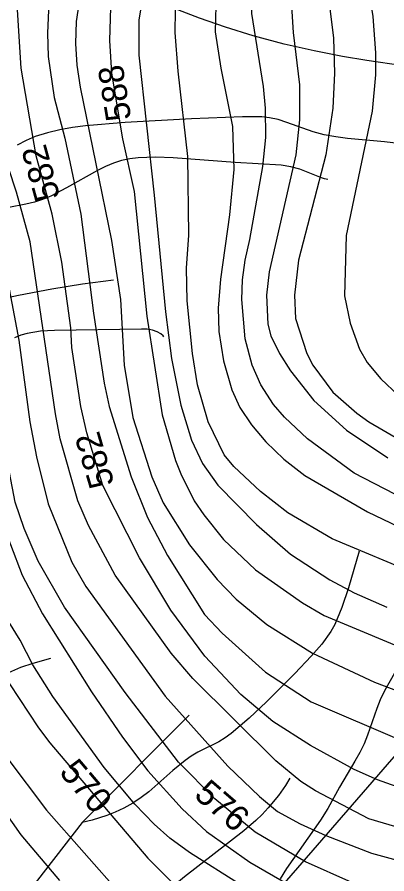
# Model space of a CAD drawing. Extents: x -709584 to -702006, y -1161789 to -1157496.
# Drawn here: x -709047.8 to -708901, y -1161172.4 to -1160832.7 of the extents above; entities that cross this region are included whole.
import ezdxf

# ---------------------------------------------------------------- set-up
doc = ezdxf.new("R2010")
doc.units = 0
for name, color, linetype in [('120_vrstevnice hlavní', 7, 'Continuous'), ('121_vrstevnice hlavní_popis', 7, 'Continuous'), ('122_vrstevnice základní', 7, 'Continuous'), ('411_akumulovaný odtok', 7, 'Continuous')]:
    doc.layers.add(name, color=color, linetype=linetype)

msp = doc.modelspace()

# ---------------------------------------------------------------- linework, layer by layer
at = {"layer": '120_vrstevnice hlavní'}
for points in [[(-708900.67, -1160565.36), (-708906.31, -1160597.76), (-708913.69, -1160630.16), (-708921.21, -1160653.3), (-708933.94, -1160685.7), (-708963.16, -1160745.88), (-708984.85, -1160787.53), (-708991.08, -1160801.42), (-708994.55, -1160810.68), (-708997.15, -1160819.93), (-708999.46, -1160833.82), (-708999.46, -1160847.71), (-708993.39, -1160903.25), (-708988.91, -1160949.54), (-708986.45, -1160968.05), (-708982.83, -1160986.56), (-708978.49, -1161000.45), (-708974.15, -1161009.71), (-708968.08, -1161018.24), (-708952.74, -1161033.86), (-708939.29, -1161045.58), (-708923.67, -1161055.85), (-708913.98, -1161060.91), (-708900.96, -1161066.7)], [(-708895.03, -1160707.69), (-708909.35, -1160738.07), (-708920.49, -1160764.1), (-708923.53, -1160773.07), (-708925.84, -1160782.33), (-708927.86, -1160794.8), (-708927.6, -1160807.53), (-708923.96, -1160827.17), (-708922.22, -1160841.05), (-708921.79, -1160854.94), (-708922.51, -1160868.82), (-708925.26, -1160887.34), (-708936.11, -1160929), (-708937.7, -1160942.88), (-708937.27, -1160952.14), (-708932.78, -1160966.03), (-708930.32, -1160970.65)], [(-708894.31, -1161154.64), (-708908.19, -1161150.59), (-708929.31, -1161139.45), (-708935.1, -1161135.84), (-708945.08, -1161127.59), (-708978.06, -1161094.9), (-708986.59, -1161084.92), (-709008.87, -1161053.97), (-709019.43, -1161034.3), (-709023.62, -1161024.46), (-709030.71, -1160999.87), (-709032.59, -1160990.04), (-709042.57, -1160921.76), (-709048.07, -1160902.09), (-709054.57, -1160882.42), (-709058.48, -1160867.67), (-709060.36, -1160852.91), (-709061.08, -1160838.16), (-709060.65, -1160823.7)], [(-709117.78, -1160829.48), (-709119.66, -1160842.5), (-709120.24, -1160855.52), (-709117.21, -1160884.16), (-709110.7, -1160908.46), (-709095.36, -1160959.08), (-709088.42, -1160993.8), (-709083.36, -1161024.17), (-709074.34, -1161055.36), (-709062.5, -1161079.58), (-709039.24, -1161114.57), (-709034.76, -1161120.51), (-708995.85, -1161166.21), (-708983.41, -1161178.65)], [(-708930.32, -1160970.65), (-708922.51, -1160981.36), (-708912.97, -1160989.75), (-708908.19, -1160993.22), (-708895.18, -1161000.74)]]:
    msp.add_lwpolyline(points, dxfattribs=at)
at = {"layer": '122_vrstevnice základní'}
for points in [[(-708893.44, -1160501.43), (-708905.01, -1160517.63), (-708917.74, -1160540.19), (-708923.38, -1160552.63), (-708928.88, -1160568.83), (-708936.54, -1160608.18), (-708944.35, -1160638.26), (-708950, -1160654.46), (-708959.69, -1160677.6), (-708965.62, -1160689.18), (-708975.31, -1160705.38), (-709010.75, -1160755.13), (-709017.4, -1160766.71), (-709020.73, -1160773.65), (-709027.09, -1160789.85), (-709032.3, -1160808.36), (-709033.75, -1160815.31), (-709035.19, -1160826.88), (-709035.77, -1160839.03), (-709035.48, -1160848.28), (-709033.02, -1160864.49)], [(-708896.48, -1160517.63), (-708903.28, -1160528.04), (-708912.82, -1160546.85), (-708920.63, -1160572.88), (-708931.34, -1160622.06), (-708935.1, -1160636.24), (-708939.44, -1160649.25), (-708949.85, -1160675.29), (-708959.69, -1160696.12), (-708968.08, -1160711.74), (-708979.36, -1160729.97), (-708995.27, -1160753.4), (-709003.95, -1160769.02), (-709014.65, -1160792.45), (-709021.59, -1160815.88), (-709024.34, -1160834.4), (-709024.63, -1160843.08), (-709024.05, -1160851.76), (-709022.75, -1160860.44), (-709010.31, -1160921.19), (-709006.7, -1160944.62), (-709005.25, -1160970.65), (-709001.78, -1160991.48), (-708994.26, -1161014.92)], [(-708887.94, -1161054.11), (-708922.66, -1161039.5), (-708940.3, -1161029.23), (-708951.15, -1161020.84), (-708961.71, -1161010.86), (-708965.62, -1161006.24), (-708971.98, -1160993.22), (-708976.18, -1160978.47), (-708978.2, -1160966.03), (-708980.23, -1160945.2), (-708980.52, -1160932.18), (-708979.65, -1160919.16), (-708979.94, -1160887.92), (-708983.8, -1160854.04), (-708985, -1160838.74), (-708984.85, -1160830.06), (-708982.83, -1160817.04), (-708973.43, -1160791.01), (-708959.69, -1160762.37), (-708954.05, -1160749.35), (-708923.96, -1160686.86), (-708911.38, -1160655.62), (-708905.16, -1160634.79), (-708899.95, -1160608.75)], [(-708898.65, -1160657.35), (-708907.9, -1160680.5), (-708959.69, -1160794.19), (-708964.75, -1160806.92), (-708968.8, -1160822.83), (-708969.09, -1160838.45), (-708966.92, -1160852.91), (-708962.29, -1160876.06), (-708961.75, -1160893.14), (-708963.45, -1160911.06), (-708967.06, -1160936.52), (-708967.93, -1160948.09), (-708967.64, -1160957.35), (-708965.91, -1160968.92), (-708962.58, -1160980.49), (-708959.4, -1160987.43), (-708954.77, -1160994.38), (-708948.98, -1161001.03), (-708941.9, -1161007.97), (-708933.51, -1161014.48), (-708908.63, -1161028.8), (-708887.37, -1161039.07)], [(-708897.78, -1161021.86), (-708913.98, -1161013.47), (-708932.49, -1160999.87), (-708941.61, -1160991.34), (-708945.95, -1160986.28), (-708951.01, -1160978.47), (-708954.48, -1160970.65), (-708957.23, -1160960.24), (-708958.53, -1160944.62), (-708958.24, -1160936.81), (-708957.23, -1160929), (-708955.35, -1160920.9), (-708950.29, -1160891.97), (-708948.98, -1160880.4), (-708949.13, -1160868.82), (-708950, -1160860.15), (-708954.62, -1160831.22), (-708954.62, -1160825.72), (-708953.18, -1160810.39), (-708948.39, -1160794.49), (-708933.94, -1160754.84), (-708914.7, -1160710.58), (-708897.63, -1160676.74)], [(-708891.13, -1160681.36), (-708902.7, -1160702.63), (-708918.46, -1160737.2), (-708930.76, -1160769.6), (-708934.52, -1160783.48), (-708938.57, -1160805.76), (-708939.29, -1160821.96), (-708938.14, -1160838.74), (-708935.68, -1160859.57), (-708935.68, -1160873.45), (-708937.12, -1160887.34), (-708947.68, -1160933.62), (-708948.84, -1160942.88), (-708948.26, -1160954.45), (-708947.1, -1160959.08), (-708943.63, -1160966.03), (-708939.29, -1160972.97), (-708930.04, -1160984.68), (-708917.02, -1160996.4), (-708900.67, -1161007.39)], [(-708911.81, -1160774.8), (-708912.74, -1160793.12), (-708906.6, -1160832.37), (-708905.45, -1160846.84), (-708905.45, -1160855.52), (-708906.89, -1160869.98), (-708917.1, -1160919.27), (-708917.86, -1160943.25), (-708915.59, -1160954.01), (-708911.81, -1160964.29), (-708908.77, -1160969.64), (-708903.42, -1160976.15), (-708896.33, -1160982.66)], [(-708893.15, -1161139.16), (-708904.72, -1161135.11), (-708913.98, -1161131.06), (-708931.34, -1161121.52), (-708946.23, -1161111.97), (-708958.96, -1161101.27), (-708973.28, -1161086.08), (-708986.73, -1161067.86), (-708999.18, -1161047.03), (-709013.78, -1161018.39), (-709020.15, -1160997.56), (-709022.46, -1160987.14), (-709026.08, -1160963.71), (-709026.51, -1160955.9), (-709029.98, -1160929.86), (-709033.89, -1160910.77), (-709040.25, -1160887.63), (-709046.18, -1160852.91), (-709047.63, -1160829.77), (-709046.47, -1160813.86), (-709042.57, -1160795.63), (-709037.22, -1160780.01)], [(-708958.82, -1161176.92), (-708979.36, -1161163.9), (-708987.17, -1161158.26), (-708993.39, -1161152.76), (-709001.06, -1161144.8), (-709013.21, -1161130.2), (-709033.6, -1161102.14), (-709041.56, -1161089.55), (-709046.62, -1161079.72), (-709056.74, -1161063.52), (-709062.29, -1161052.26), (-709067.83, -1161036.6), (-709071.06, -1161017.81), (-709078.44, -1160987.72), (-709081.91, -1160966.89), (-709088.42, -1160934.49), (-709094.21, -1160911.35), (-709096.52, -1160904.41), (-709102.02, -1160881.26), (-709104.77, -1160848.86), (-709104.33, -1160841.92), (-709101.29, -1160819.07)], [(-709125.88, -1160821.67), (-709128.2, -1160839.9), (-709128.34, -1160855.52), (-709124.58, -1160884.16), (-709119.23, -1160907.59), (-709114.75, -1160923.21), (-709108.38, -1160949.25), (-709103.46, -1160980.49), (-709099.56, -1161011.73), (-709096.38, -1161027.93), (-709091.89, -1161045.29), (-709083.5, -1161071.33), (-709080.9, -1161077.11), (-709071.5, -1161094.47), (-709051.83, -1161126.29), (-709036.06, -1161147.12), (-709006.26, -1161180.97)], [(-709030.85, -1161175.04), (-709046.18, -1161156.96), (-709080.03, -1161108.93), (-709087.55, -1161095.05), (-709097.39, -1161071.91), (-709102.89, -1161055.71), (-709109.1, -1161032.56), (-709114.17, -1161004.79), (-709117.2, -1160977.02), (-709124, -1160937.68), (-709131.23, -1160907.59), (-709137.02, -1160877.5), (-709140.49, -1160854.36), (-709140.93, -1160840.47), (-709139.48, -1160824.56)], [(-709028.97, -1161066.7), (-709039.39, -1161048.47), (-709045.03, -1161035.46), (-709048.5, -1161025.04), (-709052.55, -1161004.21), (-709056.89, -1160966.6), (-709060.94, -1160943.17), (-709066.58, -1160916.85), (-709079.16, -1160873.45), (-709082.64, -1160856.09), (-709083.21, -1160847.42), (-709083.07, -1160835.84), (-709081.62, -1160824.85)], [(-709010.75, -1160828.9), (-709011.04, -1160841.92), (-709010.31, -1160854.94), (-709005.97, -1160880.97), (-709001.34, -1160901.8), (-708996.28, -1160951.27), (-708990.21, -1160990.32), (-708984.85, -1161008.55), (-708982.83, -1161013.76), (-708977.48, -1161024.46), (-708973.72, -1161030.1), (-708965.91, -1161039.79), (-708953.18, -1161051.8)], [(-709091.6, -1160829.48), (-709092.47, -1160837.58), (-709092.62, -1160849.73), (-709091.75, -1160859.86), (-709087.99, -1160880.11), (-709079.31, -1160908.46), (-709071.35, -1160938.83), (-709067.74, -1160959.08), (-709063.83, -1160987.72), (-709058.33, -1161017.52), (-709055.15, -1161029.67), (-709045.75, -1161053.97), (-709037.65, -1161069.3), (-709018.27, -1161100.26), (-709005.97, -1161118.19), (-708995.85, -1161131.5), (-708982.25, -1161146.69), (-708972.56, -1161155.65), (-708955.35, -1161167.8), (-708936.54, -1161178.65)], [(-709070.63, -1160831.22), (-709070.92, -1160842.79), (-709070.2, -1160856.67), (-709067.3, -1160872.87), (-709060.94, -1160896.02), (-709054.14, -1160923.79), (-709047.05, -1160960.82), (-709042.71, -1160993.22), (-709040.11, -1161007.1), (-709035.48, -1161025.62), (-709026.08, -1161048.76), (-709020.44, -1161058.45), (-708989.05, -1161101.99), (-708964.17, -1161129.76), (-708951.59, -1161141.77), (-708944.35, -1161147.7)], [(-709033.02, -1160864.49), (-709028.83, -1160880.69), (-709022.46, -1160910.77), (-709017.4, -1160950.11), (-709013.21, -1160977.89), (-709011.18, -1160987.14), (-709002.5, -1161014.92), (-708995.99, -1161031.11), (-708988.04, -1161046.16), (-708973.43, -1161069.59), (-708966.34, -1161076.97), (-708949.13, -1161092.44), (-708931.05, -1161104.16), (-708894.31, -1161119.93)], [(-708994.26, -1161014.92), (-708989.77, -1161025.33), (-708979.36, -1161041.96), (-708968.37, -1161055.71), (-708960.84, -1161063.52), (-708948.69, -1161073.5), (-708930.47, -1161084.92), (-708905.88, -1161096.35), (-708893.73, -1161100.98)], [(-708953.18, -1161051.8), (-708934.52, -1161064.96), (-708925.84, -1161070.02), (-708886.79, -1161086.22), (-708873.77, -1161089.84), (-708836.16, -1161097.36), (-708819.96, -1161098.52), (-708789.3, -1161098.95), (-708764.71, -1161095.05), (-708749.23, -1161089.7), (-708741.56, -1161086.08), (-708722.18, -1161074.94), (-708710.18, -1161067.13), (-708705.11, -1161064.67), (-708701.21, -1161063.66), (-708696.58, -1161065.11), (-708695.86, -1161066.84), (-708696.15, -1161074.8), (-708697.59, -1161080.01), (-708703.67, -1161093.02), (-708718.71, -1161119.06), (-708750.68, -1161166.65), (-708757.04, -1161178.07)], [(-708914.85, -1161175.9), (-708933.36, -1161167.66), (-708953.32, -1161155.94), (-708969.23, -1161142.64), (-708983.7, -1161128.17), (-709004.82, -1161100.54), (-709028.97, -1161066.7)], [(-708944.35, -1161147.7), (-708935.39, -1161152.62), (-708925.26, -1161157.25), (-708907.04, -1161164.19), (-708896.91, -1161166.94), (-708874.64, -1161170.41), (-708866.54, -1161171.13), (-708855.25, -1161171.13), (-708837.03, -1161169.83), (-708831.82, -1161169.97), (-708827.19, -1161171.42), (-708824.88, -1161173.3)]]:
    msp.add_lwpolyline(points, dxfattribs=at)
at = {"layer": '411_akumulovaný odtok'}
msp.add_line((-708979.49, -1161109.5), (-709021.99, -1161152), dxfattribs=at)
for points in [[(-708894.49, -1160852), (-708908.99, -1160849.93), (-708918.67, -1160848.24), (-708929.8, -1160846.04), (-708941.78, -1160843.33), (-708954.01, -1160840.09), (-708965.04, -1160836.65), (-708975.42, -1160833.05), (-708985.74, -1160829.18)], [(-708896.36, -1160882.81), (-708901.97, -1160882.11), (-708916.58, -1160880.84), (-708921.27, -1160880.2), (-708925.83, -1160879.35), (-708930.23, -1160878.22), (-708940.75, -1160874.42), (-708944.18, -1160873.32), (-708947.65, -1160872.56), (-708950.59, -1160872.26), (-708958.33, -1160872.16), (-708978.55, -1160872.94), (-709004.89, -1160874.48), (-709020.62, -1160875.84), (-709025.77, -1160876.5), (-709030.84, -1160877.36), (-709035.78, -1160878.5), (-709040.56, -1160880.03), (-709044.23, -1160881.62), (-709047.8, -1160883.46)], [(-708924.49, -1160897), (-708925.71, -1160896.82), (-708926.97, -1160896.39), (-708935.5, -1160893.01), (-708939.11, -1160892), (-708942.91, -1160891.41), (-708961.24, -1160890.31), (-708985.82, -1160888.48), (-708992.8, -1160888.22), (-708999.67, -1160888.41), (-709003.02, -1160888.8), (-709006.3, -1160889.48), (-709009.55, -1160890.53), (-709012.72, -1160891.88), (-709015.84, -1160893.43), (-709028.15, -1160900.42), (-709034.42, -1160903.65), (-709037.65, -1160904.99), (-709040.92, -1160906.05), (-709044.26, -1160906.89), (-709051.1, -1160908.12), (-709061.65, -1160909.34), (-709096.99, -1160912)], [(-709009.49, -1160937), (-709021.78, -1160938.61), (-709033.93, -1160940.54), (-709047.26, -1160943.04), (-709061.13, -1160945.97)], [(-708989.49, -1160959.5), (-708989.8, -1160959.01), (-708990.71, -1160958.27), (-708992.16, -1160957.47), (-708994.07, -1160956.8), (-708996.1, -1160956.47), (-708998.38, -1160956.36), (-709032.93, -1160956.89), (-709038.43, -1160957.26), (-709043.78, -1160958.11), (-709046.35, -1160958.83), (-709048.8, -1160959.81)], [(-708911.99, -1161044.5), (-708916.21, -1161059.04), (-708918.82, -1161066.75), (-708921.7, -1161073.59), (-708923.21, -1161076.3), (-708926.86, -1161081.33), (-708930.98, -1161086.07), (-708937.56, -1161092.94), (-708948.84, -1161104.18), (-708955.7, -1161110.71), (-708962.78, -1161116.72), (-708965.23, -1161118.49), (-708967.76, -1161120.06), (-708976.06, -1161124.2), (-708978.62, -1161125.76), (-708981.11, -1161127.52), (-708985.93, -1161131.42), (-708995.52, -1161139.87), (-708998.5, -1161142.13), (-709001.86, -1161144.34), (-709005.46, -1161146.35), (-709008.85, -1161147.92), (-709012.17, -1161149.22), (-709017.95, -1161151.06), (-709021.99, -1161152)], [(-708859.49, -1161049.5), (-708865.18, -1161058.29), (-708869.11, -1161064.76), (-708872.83, -1161071.51), (-708874.36, -1161074.69), (-708875.54, -1161077.59), (-708876.46, -1161080.43), (-708877.95, -1161086.24), (-708879.95, -1161095.03), (-708881.5, -1161100.77), (-708882.45, -1161103.56), (-708883.59, -1161106.26), (-708885.04, -1161108.98), (-708886.69, -1161111.61), (-708890.39, -1161116.68), (-708896.46, -1161124.04), (-708946.99, -1161182)], [(-709034.49, -1161087), (-709041.52, -1161088.96), (-709046.44, -1161090.62), (-709051.19, -1161092.66), (-709053.25, -1161093.81), (-709058.24, -1161097.42), (-709074.07, -1161110.49), (-709077.33, -1161112.85), (-709080.72, -1161114.83), (-709082.5, -1161115.58), (-709086.33, -1161116.52), (-709090.34, -1161116.94), (-709098.55, -1161117.29), (-709102.61, -1161117.62), (-709106.52, -1161118.39), (-709108.38, -1161119.06), (-709110.2, -1161119.91), (-709114.33, -1161122.44), (-709118.79, -1161125.63), (-709126.99, -1161132)], [(-708893.93, -1161085.83), (-708901.89, -1161099.87), (-708903.63, -1161103.42), (-708905.04, -1161106.86), (-708908.68, -1161117.37), (-708910.05, -1161120.8), (-708911.76, -1161124.33), (-708913.68, -1161127.77), (-708919.76, -1161137.97), (-708924.44, -1161146.47), (-708927.38, -1161151.07), (-708940.79, -1161170.25), (-708943.4, -1161174.4)], [(-708939.49, -1161134.5), (-708941.17, -1161137.34), (-708943.97, -1161141.34), (-708948.07, -1161146.25), (-708950.53, -1161148.81), (-708953.05, -1161151.23), (-708957.75, -1161155.29), (-708981.3, -1161173.64), (-708987.59, -1161178.79), (-708991.62, -1161182.39), (-708995.56, -1161186.33), (-708999.36, -1161190.43), (-709015.96, -1161209.35), (-709019.74, -1161213.49), (-709022.01, -1161215.69), (-709024.62, -1161217.94), (-709027.47, -1161220.11), (-709030.46, -1161222.05), (-709035.98, -1161224.85), (-709040.25, -1161226.5), (-709041.99, -1161227)], [(-709021.99, -1161152), (-709051.1, -1161189.61), (-709054.13, -1161193.22), (-709056.31, -1161195.4), (-709058.76, -1161197.18), (-709061.49, -1161198.55), (-709064.41, -1161199.61), (-709067.95, -1161200.2), (-709069.81, -1161200.22), (-709071.61, -1161200.02), (-709073.25, -1161199.58), (-709075.58, -1161198.34), (-709076.99, -1161197)]]:
    msp.add_lwpolyline(points, dxfattribs=at)

# ---------------------------------------------------------------- texts
at = {"layer": '121_vrstevnice hlavní_popis'}
for s, rotation, p in [('588', 99.1682, (-709002.4, -1160873.05)), ('582', 105.3775, (-709030.64, -1160904.03)), ('582', 106.4684, (-709009.07, -1161017.72)), ('570', 310.34, (-709031.4, -1161132.26)), ('576', 319.2774, (-708977.99, -1161141.79))]:
    msp.add_text(s, height=10, rotation=rotation, dxfattribs=at).set_placement(p)

doc.saveas('drawing.dxf')
